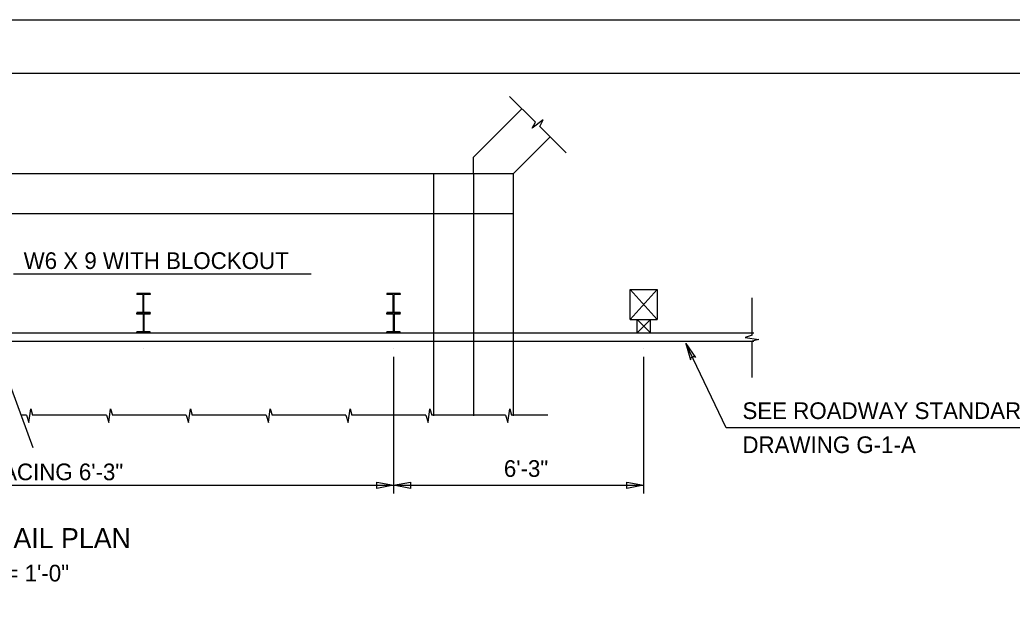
# Model space of a CAD drawing. Extents: x 0 to 90.7, y 0 to 62.8.
# Drawn here: x 26.31 to 51.11, y 43.93 to 58.67 of the extents above; entities that cross this region are included whole.
import ezdxf

# ---------------------------------------------------------------- set-up
doc = ezdxf.new("R2010")
doc.units = 0
for name, color, linetype in [('BORDER_ANNO_Cutsheet', 7, 'Continuous'), ('BRDG_ANNO_Anno-Sheet', 7, 'Continuous'), ('BRDG_ANNO_General-Notes', 7, 'Continuous'), ('BRDG_BASE_Obj-Line', 7, 'Continuous')]:
    doc.layers.add(name, color=color, linetype=linetype)

msp = doc.modelspace()

# ---------------------------------------------------------------- linework, layer by layer
at = {"layer": 'BORDER_ANNO_Cutsheet'}
msp.add_lwpolyline([(0, 58.667), (90.667, 58.667), (90.667, 0), (0, 0)], close=True, dxfattribs=at)
at = {"layer": 'BRDG_ANNO_Anno-Sheet'}
msp.add_lwpolyline([(4, 57.333), (89.333, 57.333), (89.333, 1.333), (4, 1.333)], close=True, dxfattribs=at)
at = {"layer": 'BRDG_ANNO_General-Notes'}
for p, q in [((33.592, 52.312), (26.153, 52.312)), ((43.962, 48.466), (42.954, 50.578)), ((42.954, 50.578), (43.075, 50.169)), ((42.954, 50.578), (43.195, 50.227)), ((35.653, 50.241), (35.653, 46.824)), ((41.903, 50.241), (41.903, 46.824)), ((51.779, 48.466), (43.962, 48.466)), ((16.903, 47.032), (35.653, 47.032)), ((35.233, 46.953), (35.233, 47.111)), ((35.233, 47.111), (35.653, 47.032)), ((35.653, 47.032), (35.233, 46.953)), ((35.653, 47.032), (36.073, 47.111)), ((35.653, 47.032), (41.903, 47.032)), ((36.073, 46.953), (35.653, 47.032)), ((36.073, 47.111), (36.073, 46.953)), ((41.483, 46.953), (41.483, 47.111)), ((41.483, 47.111), (41.903, 47.032)), ((41.903, 47.032), (41.483, 46.953))]:
    msp.add_line(p, q, dxfattribs=at)
msp.add_arc((43.149, 50.17), 0.0741, 50.7659, 180.3304, dxfattribs=at)
at = {"layer": 'BRDG_BASE_Obj-Line'}
for p, q in [((38.554, 56.752), (39.198, 56.107)), ((38.861, 56.445), (37.653, 55.237)), ((39.39, 56.17), (39.117, 55.961)), ((39.117, 55.961), (39.198, 56.107)), ((39.304, 56.002), (39.39, 56.17)), ((39.304, 56.002), (39.965, 55.341)), ((39.568, 55.738), (38.653, 54.823)), ((37.653, 54.823), (37.653, 55.237)), ((24.144, 54.823), (38.653, 54.823)), ((36.653, 54.823), (36.653, 48.766)), ((37.653, 54.823), (37.653, 48.766)), ((38.653, 48.766), (38.653, 54.823)), ((24.508, 53.823), (38.653, 53.823)), ((41.57, 51.927), (42.237, 51.927)), ((41.57, 51.177), (41.57, 51.927)), ((41.57, 51.927), (42.237, 51.927)), ((41.57, 51.177), (42.237, 51.927)), ((42.237, 51.177), (41.57, 51.927)), ((42.237, 51.927), (42.237, 51.177)), ((29.57, 51.823), (29.237, 51.823)), ((29.237, 51.823), (29.237, 51.802)), ((29.383, 51.802), (29.237, 51.802)), ((29.393, 51.364), (29.393, 51.792)), ((29.414, 51.364), (29.414, 51.792)), ((29.57, 51.802), (29.424, 51.802)), ((29.57, 51.823), (29.57, 51.802)), ((35.82, 51.823), (35.487, 51.823)), ((35.487, 51.823), (35.487, 51.802)), ((35.633, 51.802), (35.487, 51.802)), ((35.643, 51.364), (35.643, 51.792)), ((35.664, 51.364), (35.664, 51.792)), ((35.82, 51.802), (35.674, 51.802)), ((35.82, 51.823), (35.82, 51.802)), ((44.617, 50.782), (44.617, 51.716)), ((29.237, 51.354), (29.237, 51.333)), ((29.383, 51.354), (29.237, 51.354)), ((29.57, 51.354), (29.424, 51.354)), ((29.57, 51.354), (29.57, 51.333)), ((35.487, 51.354), (35.487, 51.333)), ((35.633, 51.354), (35.487, 51.354)), ((35.82, 51.354), (35.674, 51.354)), ((35.82, 51.354), (35.82, 51.333)), ((29.57, 51.333), (29.237, 51.333)), ((29.57, 51.333), (29.237, 51.333)), ((29.237, 51.312), (29.237, 51.333)), ((29.383, 51.312), (29.237, 51.312)), ((29.393, 51.302), (29.393, 50.875)), ((29.414, 51.302), (29.414, 50.875)), ((29.57, 51.312), (29.424, 51.312)), ((29.57, 51.312), (29.57, 51.333)), ((35.82, 51.333), (35.487, 51.333)), ((35.82, 51.333), (35.487, 51.333)), ((35.487, 51.312), (35.487, 51.333)), ((35.633, 51.312), (35.487, 51.312)), ((35.643, 51.302), (35.643, 50.875)), ((35.664, 51.302), (35.664, 50.875)), ((35.82, 51.312), (35.674, 51.312)), ((35.82, 51.312), (35.82, 51.333)), ((41.57, 51.177), (42.237, 51.177)), ((41.737, 50.843), (41.737, 51.177)), ((41.737, 51.177), (42.07, 50.843)), ((42.07, 51.177), (41.737, 50.843)), ((42.07, 50.843), (42.07, 51.177)), ((29.237, 50.843), (29.237, 50.864)), ((29.383, 50.864), (29.237, 50.864)), ((29.57, 50.864), (29.424, 50.864)), ((29.57, 50.843), (29.57, 50.864)), ((35.487, 50.843), (35.487, 50.864)), ((35.633, 50.864), (35.487, 50.864)), ((35.82, 50.864), (35.674, 50.864)), ((35.82, 50.843), (35.82, 50.864)), ((25.592, 50.843), (44.656, 50.843)), ((25.668, 50.635), (44.656, 50.635)), ((29.57, 50.843), (29.237, 50.843)), ((35.82, 50.843), (35.487, 50.843)), ((44.617, 50.782), (44.437, 50.723)), ((44.437, 50.723), (44.778, 50.678)), ((44.778, 50.678), (44.617, 50.632)), ((44.617, 49.721), (44.617, 50.632)), ((29.403, 50.449), (29.403, 50.449)), ((35.653, 50.449), (35.653, 50.449)), ((41.903, 50.449), (41.903, 50.449)), ((26.641, 47.963), (25.951, 49.858)), ((26.538, 48.602), (26.583, 48.943)), ((26.583, 48.943), (26.63, 48.782)), ((28.533, 48.602), (28.579, 48.943)), ((28.579, 48.943), (28.625, 48.782)), ((30.529, 48.602), (30.574, 48.943)), ((30.574, 48.943), (30.62, 48.782)), ((32.524, 48.602), (32.569, 48.943)), ((32.569, 48.943), (32.615, 48.782)), ((34.519, 48.602), (34.564, 48.943)), ((34.564, 48.943), (34.61, 48.782)), ((36.514, 48.602), (36.56, 48.943)), ((36.56, 48.943), (36.606, 48.782)), ((38.51, 48.602), (38.555, 48.943)), ((38.555, 48.943), (38.601, 48.782)), ((26.48, 48.782), (26.343, 48.782)), ((26.48, 48.782), (26.538, 48.602)), ((27.541, 48.782), (26.63, 48.782)), ((28.475, 48.782), (27.541, 48.782)), ((28.475, 48.782), (28.533, 48.602)), ((29.536, 48.782), (28.625, 48.782)), ((30.47, 48.782), (29.536, 48.782)), ((30.47, 48.782), (30.529, 48.602)), ((31.531, 48.782), (30.62, 48.782)), ((32.466, 48.782), (31.531, 48.782)), ((32.466, 48.782), (32.524, 48.602)), ((33.526, 48.782), (32.615, 48.782)), ((34.461, 48.782), (33.526, 48.782)), ((34.461, 48.782), (34.519, 48.602)), ((35.521, 48.782), (34.61, 48.782)), ((36.456, 48.782), (35.521, 48.782)), ((36.456, 48.782), (36.514, 48.602)), ((37.517, 48.782), (36.606, 48.782)), ((38.451, 48.782), (37.517, 48.782)), ((38.451, 48.782), (38.51, 48.602)), ((39.512, 48.782), (38.601, 48.782))]:
    msp.add_line(p, q, dxfattribs=at)
for centre, start, end in [((29.383, 51.792), 0, 90), ((29.424, 51.792), 90, 180), ((35.633, 51.792), 0, 90), ((35.674, 51.792), 90, 180), ((29.383, 51.364), 270, 0), ((29.424, 51.364), 180, 270), ((35.633, 51.364), 270, 0), ((35.674, 51.364), 180, 270), ((29.383, 51.302), 0, 90), ((29.424, 51.302), 90, 180), ((35.633, 51.302), 0, 90), ((35.674, 51.302), 90, 180), ((29.383, 50.875), 270, 360), ((29.424, 50.875), 180, 270), ((35.633, 50.875), 270, 360), ((35.674, 50.875), 180, 270)]:
    msp.add_arc(centre, 0.0104, start, end, dxfattribs=at)

# ---------------------------------------------------------------- texts
at = {"layer": 'BRDG_ANNO_General-Notes'}
for s, height, p in [('W6 X 9 WITH BLOCKOUT', 0.41667, (26.406, 52.438)), ('SEE ROADWAY STANDARD', 0.41667, (44.372, 48.687)), ('DRAWING G-1-A', 0.41667, (44.372, 47.836)), ('6\'-3"', 0.4167, (38.409, 47.241)), ('POST SPACING 6\'-3"', 0.41667, (23.452, 47.157)), ('GUARDRAIL PLAN', 0.5, (23.254, 45.459)), ('3/8" = 1\'-0"', 0.41667, (24.825, 44.626))]:
    msp.add_text(s, height=height, dxfattribs=at).set_placement(p)

doc.saveas('drawing.dxf')
